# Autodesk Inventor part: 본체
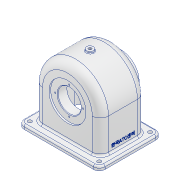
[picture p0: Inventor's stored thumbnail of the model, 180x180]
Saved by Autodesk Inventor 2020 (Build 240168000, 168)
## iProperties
Created: 2022-09
Part Number: 본체
Material: 알루미늄 6061
Document SubType Name: Modeling
Designer: Administrator
Density: 2.7 g/cm^3
Appearance: 알루미늄 - 평지
Mass: 785.263 g
Surface Area: 1042.64 cm^2
Volume: 290.838 cm^3
Author: Administrator
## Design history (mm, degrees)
sketch "스케치1"
  geometry: L1 (70, -54)-(-70, -54); L2 (-70, -54)-(-70, 54); L3 (-70, 54)-(70, 54); L4 (70, 54)-(70, -54); L5 (70, -54)-(-70, 54); L6 (-70, -54)-(70, 54); 1 further point
  constraints: 12 end point, 2 midpoint, 2 parallel, 1 horizontal, 1 perpendicular
  dimensions: "d0" = 140 distance of L1.start L1.end; "d1" = 108 distance of L3.end L1.start
extrude "돌출1" new body sketch "스케치1" distance "d2" = 7; taper "d3" = 0 deg
sketch "스케치3" dims "d5" = 114
  geometry: L1 (70, 0)-(-70, 0) reference; L2 (-70, 0)-(-70, 7) reference; L3 (70, 7)-(-70, 7) reference; L4 (70, 0)-(70, 7) reference; L5 (70, 7)-(-70, 7) reference; L6 (-57, 7)-(57, 7); L7 (57, 7)-(57, 64); L8 (57, 64)-(-57, 64); L9 (-57, 64)-(-57, 7); 3 further points
  constraints: 8 end point, 2 parallel, 1 horizontal, 1 midpoint, 1 perpendicular, 1 point on line, 1 vertical alignment, 3 other
  dimensions: "d4" = 64 distance between parallel lines of L1 L8
extrude "돌출2" join sketch "스케치3" stored distance "d6" = 78; taper "d7" = 0 deg
sketch "스케치4"
  geometry: L1 (-70, 0)-(70, 0) reference; C1 r 32 at (0, 64); A1 r 57 centre (0, 64) between (57, 64) and (-57, 64) reference; 2 further points
  constraints: 1 centre point, 1 coincident, 1 midpoint, 1 vertical alignment
  dimensions: "d8" = 64 diameter of C1
extrude "돌출3" cut sketch "스케치4" distance "d9" = 3; taper "d10" = 0 deg
sketch "스케치5"
  geometry: L1 (64, 39)-(7, 39) reference; L2 (64, -39)-(64, 39) reference; L3 (64, 20)-(64, -34); L4 (64, 20)-(92, 20); L5 (92, 20)-(100.083, 34); L6 (100.083, 34)-(116, 34); L7 (116, 34)-(116, -34); L8 (116, -34)-(64, -34); L9 (0, -54)-(7, -54) reference; L10 (32, 39)-(96, 39) reference; L11 (121, -39)-(121, 39) reference; L12 (0, -54)-(0, 54) reference; 3 further points
  constraints: 12 end point, 2 perpendicular, 1 collinear, 1 horizontal, 1 parallel
  dimensions: "d11" = 20 distance between parallel lines of L9 L8; "d12" = 5 distance between parallel lines of L10 L6; "d13" = 60 deg angle of L4 L5; "d14" = 56 diameter of L4.end L2; "d15" = 14 distance between parallel lines of L4 L6; "d16" = 5 distance between parallel lines of L11 L7; "d17" = 64 distance between parallel lines of L12 L3
revolve "회전1" sketch "스케치5" stored, may be unused: angle "d18" = 90 deg
sketch "스케치7"
  geometry: L1 (52, 34)-(-52, 34); L2 (-52, 34)-(-52, -34); L3 (-52, -34)-(52, -34); L4 (52, -34)-(52, 34); L5 (52, 34)-(-52, -34); L6 (-52, 34)-(52, -34); 1 further point
  constraints: 12 end point, 2 midpoint, 2 parallel, 1 horizontal, 1 perpendicular
  dimensions: "d20" = 104 distance of L2.end L3.end; "d21" = 68 distance of L3.end L1.start
extrude "돌출4" cut sketch "스케치7" stored distance "d22" = 5; taper "d23" = 0 deg
sketch "스케치8"
  geometry: L1 (64, 39)-(7, 39) reference; L2 (92, 20)-(36, 20) reference; L3 (100.083, 34)-(27.917, 34) reference; L4 (92, 20)-(36, 20) reference; L5 (84, 20)-(64, 20); L6 (64, 20)-(64, 36); L7 (64, -39)-(64, 39) reference; L8 (64, 36)-(84, 36); L9 (84, 36)-(84, 20); 6 further points
  constraints: 8 end point, 2 midpoint, 2 point on line, 1 horizontal, 1 perpendicular
  dimensions: "d24" = 16 distance of L8.end L5.start; "d26" = 40 diameter of L9 L6; "d27" = 20 distance of L5.start L5.end
revolve "회전2" sketch "스케치8" stored, may be unused: angle "d28" = 90 deg
sketch "스케치9"
  geometry: C1 r 31 at (0, 64); A1 r 57 centre (0, 64) between (57, 64) and (-57, 64) reference; 1 further point
  constraints: 1 centre point, 1 coincident
  dimensions: "d29" = 62 diameter of C1
extrude "돌출5" join sketch "스케치9" distance "d30" = 15; taper "d31" = 0 deg
sketch "스케치10"
  geometry: C1 r 31 at (0, 0) reference; C2 r 20 at (0, 0); 1 further point
  constraints: 1 centre point, 1 coincident
  dimensions: "d32" = 40 diameter of C2
extrude "돌출6" cut sketch "스케치10" distance "d33" = 16; taper "d34" = 0 deg
sketch "스케치11"
  geometry: C1 r 20 at (0, 0) reference; C2 r 17.5 at (0, 0); 1 further point
  constraints: 1 centre point, 1 coincident
  dimensions: "d35" = 35 diameter of C2
extrude "돌출7" cut sketch "스케치11" distance "d36" = 5; taper "d37" = 0 deg
node "작업 평면1"
sketch "스케치12"
  geometry: C1 r 6 at (0, 0); 1 further point
  constraints: 1 centre point, 1 coincident
  dimensions: "d39" = 12 diameter of C1
extrude "돌출8" join sketch "스케치12" stored distance "d40" = 5; taper "d41" = 0 deg
sketch "스케치13"
  geometry: C1 r 6 at (0, 0) reference; 2 further points
  constraints: 1 coincident
hole "구멍1" sketch "스케치13" at (0, 0) diameter "d42" = 5.1881; stored, may be unused: countersink angle "d46" = 90 deg, drill point angle "d48" = 118 deg; dims "d43" = 12, "d44" = 4, "d45" = 2, "d47" = 16
sketch "스케치14" dims "d49" = 48
  geometry: L1 (57, -57)-(57, 0) reference; C1 r 32 at (0, 0) reference; 3 further points
  constraints: 1 coincident, 1 vertical alignment, 2 other
  dimensions: "d50" = 57 distance from line of L1 point (0, 24)
hole "구멍2" sketch "스케치14" at (0, 24) diameter "d51" = 2.459; stored, may be unused: countersink angle "d55" = 90 deg, drill point angle "d57" = 118 deg; dims "d52" = 7, "d53" = 4, "d54" = 2, "d56" = 9
sketch "스케치15"
  geometry: C1 r 17.5 at (0, 0) reference; C2 r 24 at (0, 0); C3 r 1.23 at (0, 24) reference; 2 further points
  constraints: 2 coincident, 1 centre point
  dimensions: "d61" = 24 radius of C2
hole "구멍3" sketch "스케치15" at (0, 24) diameter "d62" = 2.459; stored, may be unused: countersink angle "d66" = 90 deg, drill point angle "d68" = 118 deg; dims "d63" = 7, "d64" = 4, "d65" = 2, "d67" = 9
sketch "스케치16"
  geometry: L1 (0, 57)-(78, 57) reference; L2 (0, 0)-(0, 57) reference; L3 (-15, -7)-(93, -7) reference; 3 further points
  constraints: 1 midpoint, 1 vertical alignment, 1 other
  dimensions: "d72" = 17 distance from line of L3 point (39, 10)
feature "엠보싱1" sketch "스케치16" dims "d0" = 140, "d1" = 108, "d73" = 0.5, "d74" = 0
fillet "모깎기1" dims "d75" = 9
fillet "모깎기2" dims "d76" = 0.6
chamfer "모따기1" distance "d77" = 1; stored, may be unused: second distance "d78" = 2, angle "d79" = 45 deg
fillet "모깎기3" dims "d80" = 14
fillet "모깎기4" dims "d81" = 10
sketch "스케치17"
  geometry: A1 r 10 centre (-60, 44) between (-60, 54) and (-70, 44) reference; A2 r 10 centre (-60, -44) between (-70, -44) and (-60, -54) reference; A3 r 10 centre (60, -44) between (60, -54) and (70, -44) reference; A4 r 10 centre (60, 44) between (70, 44) and (60, 54) reference; 1 further point
hole "구멍4" sketch "스케치17" at (-60, -44), (-60, 44), (60, 44), (60, -44) diameter "d82" = 6.6; stored, may be unused: countersink angle "d86" = 90 deg, drill point angle "d88" = 118 deg; dims "d83" = 7, "d84" = 4, "d85" = 2, "d87" = 9
fillet "모깎기5" dims "d89" = 3
fillet "모깎기6" dims "d90" = 1
fillet "모깎기7" dims "d91" = 3
node "솔리드1"
pattern_circular "원형 패턴1" dims angle "d59" = 360 deg
pattern_circular "원형 패턴2" dims angle "d70" = 360 deg
node "투영된 루프1"
node "투영된 루프2"
feature "A9D066F2-1C7D-4E18-AEED-F7BC21143FA4" dims "d82" = 6.6, "d83" = 7, "d84" = 4, "d85" = 2, "d86" = 90 deg, "d87" = 9, "d88" = 118 deg
other parameters: "d38" = 124
